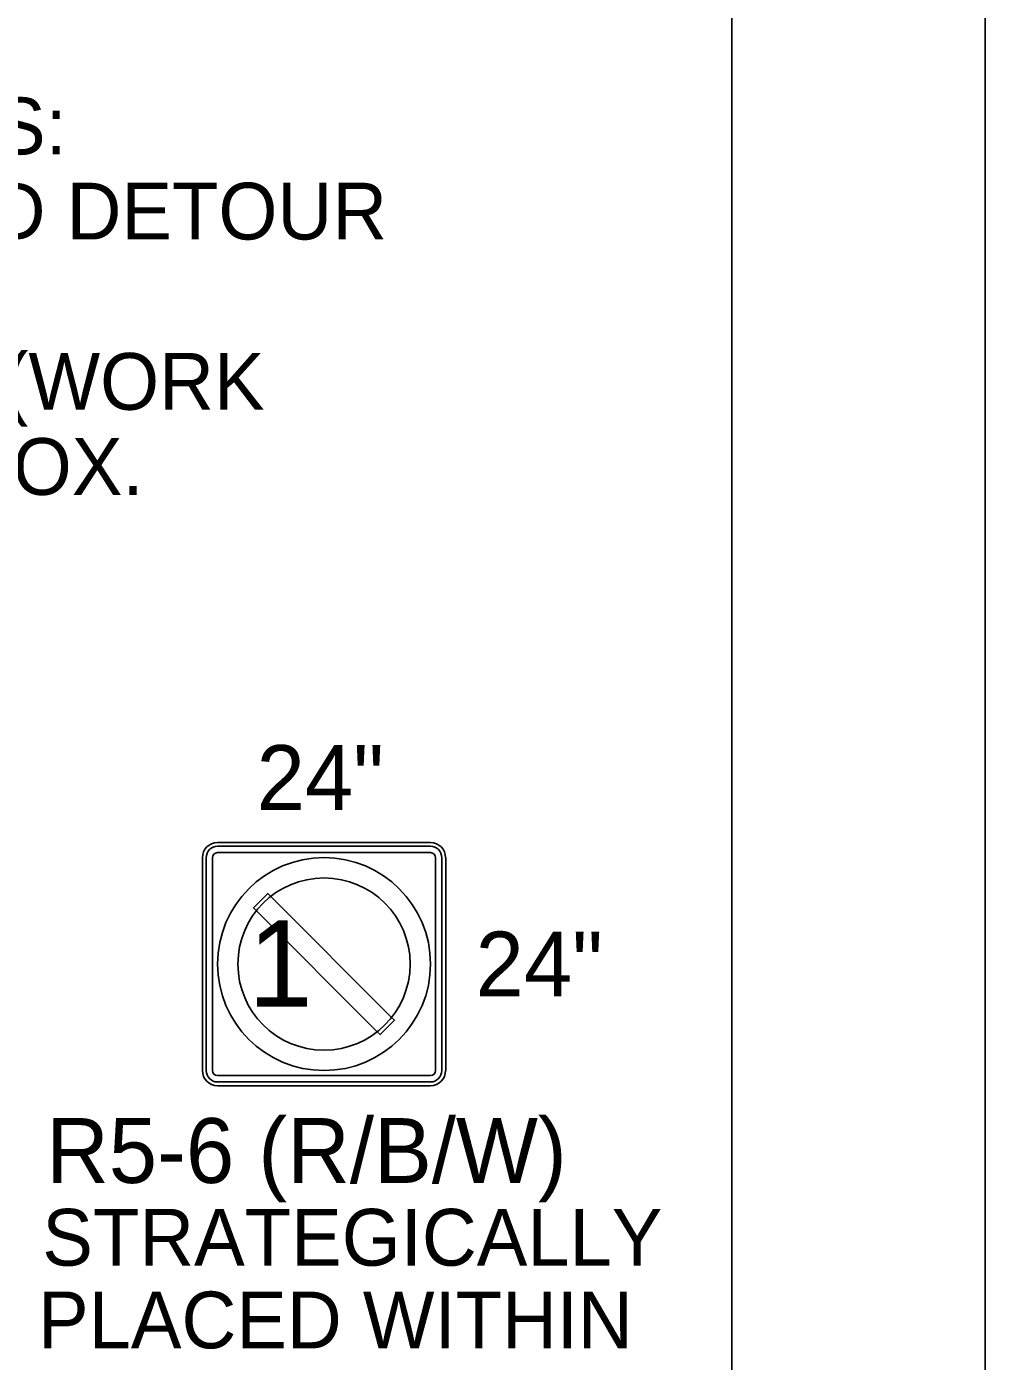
# Model space of a CAD drawing. Extents: x 99958 to 100136, y 99935 to 100013.
# Drawn here: x 100014.88 to 100016.062, y 100001.262 to 100002.908 of the extents above; entities that cross this region are included whole.
import ezdxf

# ---------------------------------------------------------------- set-up
doc = ezdxf.new("R2010")
doc.units = 0
for name, color, linetype in [('SH_GI_GeneralNotesBodyText', 7, 'Continuous'), ('SH_GI_PlotLimits', 7, 'Continuous'), ('SH_GI_SheetBorder', 7, 'Continuous'), ('TR_SN_ConstructionSigns', 7, 'Continuous')]:
    doc.layers.add(name, color=color, linetype=linetype)

msp = doc.modelspace()

# ---------------------------------------------------------------- linework, layer by layer
at = {"layer": 'SH_GI_PlotLimits'}
msp.add_lwpolyline([(99999.0625, 99999.6875), (100016.0625, 99999.6875), (100016.0625, 100010.6875), (99999.0625, 100010.6875)], close=True, dxfattribs=at)
at = {"layer": 'SH_GI_SheetBorder'}
msp.add_line((100015.75, 100010.375), (100015.75, 100000), dxfattribs=at)
at = {"layer": 'TR_SN_ConstructionSigns'}
for p, q in [((100015.3783, 100001.9019), (100015.1158, 100001.9019)), ((100015.1158, 100001.9019), (100015.3783, 100001.9019)), ((100015.3783, 100001.9019), (100015.1158, 100001.9019)), ((100015.3783, 100001.8972), (100015.1158, 100001.8972)), ((100015.0971, 100001.8831), (100015.0971, 100001.6206)), ((100015.0971, 100001.6206), (100015.0971, 100001.8831)), ((100015.0971, 100001.8831), (100015.0971, 100001.6206)), ((100015.1018, 100001.8831), (100015.1018, 100001.6206)), ((100015.1096, 100001.6206), (100015.1096, 100001.8831)), ((100015.1158, 100001.8894), (100015.3783, 100001.8894)), ((100015.3846, 100001.8831), (100015.3846, 100001.6206)), ((100015.3924, 100001.6206), (100015.3924, 100001.8831)), ((100015.3971, 100001.6206), (100015.3971, 100001.8831)), ((100015.3971, 100001.8831), (100015.3971, 100001.6206)), ((100015.3971, 100001.6206), (100015.3971, 100001.8831)), ((100015.3783, 100001.6144), (100015.1158, 100001.6144)), ((100015.1158, 100001.6066), (100015.3783, 100001.6066)), ((100015.1158, 100001.6019), (100015.3783, 100001.6019)), ((100015.3783, 100001.6019), (100015.1158, 100001.6019)), ((100015.1158, 100001.6019), (100015.3783, 100001.6019))]:
    msp.add_line(p, q, dxfattribs=at)
msp.add_lwpolyline([(100015.3305, 100001.6861), (100015.1813, 100001.8353), (100015.1778, 100001.8389), (100015.1601, 100001.8212), (100015.3128, 100001.6685), (100015.3164, 100001.6649), (100015.3341, 100001.6826), (100015.3305, 100001.6861)], dxfattribs=at)
for radius in [0.1313, 0.1062]:
    msp.add_circle((100015.2471, 100001.7519), radius, dxfattribs=at)
for centre, radius, start, end in [((100015.1158, 100001.8831), 0.0187, 90, 180), ((100015.1158, 100001.8831), 0.0187, 90, 180), ((100015.1158, 100001.8831), 0.0187, 90, 180), ((100015.1158, 100001.8831), 0.0141, 90, 180), ((100015.3783, 100001.8831), 0.0187, 0, 90), ((100015.3783, 100001.8831), 0.0187, 0, 90), ((100015.3783, 100001.8831), 0.0187, 0, 90), ((100015.3783, 100001.8831), 0.0141, 0, 90), ((100015.1158, 100001.8831), 0.00625, 90, 180), ((100015.3783, 100001.8831), 0.00625, 0, 90), ((100015.1158, 100001.6206), 0.0187, 180, 270), ((100015.1158, 100001.6206), 0.0187, 180, 270), ((100015.1158, 100001.6206), 0.0187, 180, 270), ((100015.1158, 100001.6206), 0.0141, 180, 270), ((100015.1158, 100001.6206), 0.00625, 180, 270), ((100015.3783, 100001.6206), 0.0141, 270, 0), ((100015.3783, 100001.6206), 0.00625, 270, 0), ((100015.3783, 100001.6206), 0.0187, 270, 0), ((100015.3783, 100001.6206), 0.0187, 270, 0), ((100015.3783, 100001.6206), 0.0187, 270, 0)]:
    msp.add_arc(centre, radius, start, end, dxfattribs=at)

# ---------------------------------------------------------------- texts
at = {"layer": 'SH_GI_GeneralNotesBodyText'}
for s, p in [('12. BICYCLIST ACCOMMODATIONS, WHERE FACILITY OPEN TO BICYCLES:', (100011.549, 100002.7506)), ('(A) BICYCLES PROHIBITED VIA R5-601 & R5-6 SIGNS. PROVIDE SIGNED DETOUR ', (100011.689, 100002.6456)), ('(B) BICYCLES PROHIBITED VIA R5-6 SIGNS. PROVIDE FREE SHUTTLE (WORK ', (100011.689, 100002.4356)), ('TRUCK, VAN, OR BUS OK) + CONTACT INFORMATION OR PHONE BOX.', (100011.839, 100002.3306))]:
    msp.add_text(s, height=0.07, rotation=360, dxfattribs=at).set_placement(p)
at = {"layer": 'TR_SN_ConstructionSigns'}
for s, height, p in [('24"', 0.08, (100015.164, 100001.9419)), ('24"', 0.08, (100015.434, 100001.7119)), ('R5-6 (R/B/W)', 0.08, (100014.9045, 100001.4819)), ('STRATEGICALLY', 0.07, (100014.8997, 100001.3799)), ('PLACED WITHIN', 0.07, (100014.8944, 100001.2779))]:
    msp.add_text(s, height=height, rotation=360, dxfattribs=at).set_placement(p)
msp.add_text('1', height=0.1065, dxfattribs=at).set_placement((100015.1538, 100001.6994))

doc.saveas('drawing.dxf')
